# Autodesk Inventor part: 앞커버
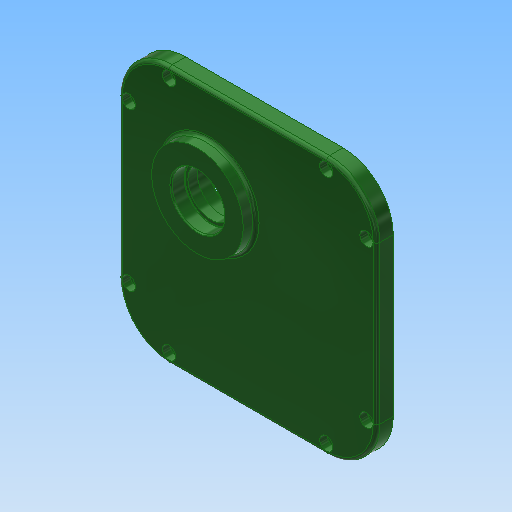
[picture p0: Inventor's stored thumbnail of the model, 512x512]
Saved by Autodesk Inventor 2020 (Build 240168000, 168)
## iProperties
Created: 2016-12
Part Number: 앞커버
Material: 알루미늄 6061
Document SubType Name: Modeling
Designer: mduedu
Density: 2.71 g/cm^3
Mass: 790.587 g
Surface Area: 580.683 cm^2
Volume: 291.729 cm^3
Appearance: 매끄러움 - 짙은 산림 녹색
Author: mduedu
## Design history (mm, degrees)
sketch "스케치1"
  geometry: L1 (-54, 50)-(-54, -44); L2 (-24, 80)-(70, 80); L3 (100, 50)-(100, -44); L4 (70, -74)-(-24, -74); A1 r 30 centre (-24, -44) between (-54, -44) and (-24, -74); A2 r 30 centre (70, 50) between (100, 50) and (70, 80); A3 r 30 centre (70, -44) between (70, -74) and (100, -44); A4 r 30 centre (-24, 50) between (-24, 80) and (-54, 50); 1 further point
  constraints: 8 end point, 8 point on circle, 8 tangent, 4 centre point, 3 equal radius, 3 perpendicular, 1 horizontal
  dimensions: "d89" = 30 radius of A2; "d90" = 100 distance from line of L3 point (0, 0); "d91" = 154 distance between parallel lines of L4 L2; "d92" = 80 distance from line of point (0, 0) L2
extrude "돌출1" new body sketch "스케치1" distance "d3" = 14; taper "d4" = 0 deg
sketch "스케치2"
  geometry: C1 r 21 at (0, 26); 1 further point
  constraints: 1 centre point, 1 vertical alignment
  dimensions: "d5" = 42 diameter of C1; "d7" = 26 distance of C1.centre point (0, 0)
extrude "돌출2" join sketch "스케치2" distance "d8" = 3; taper "d9" = 0 deg
sketch "스케치3"
  geometry: C1 r 15 at (0, -28.87); C2 r 21 at (0, 26) reference; C3 r 15 at (-54.87, 26); 1 further point
  constraints: 2 centre point, 1 horizontal alignment, 1 vertical alignment
  dimensions: "d10" = 30 diameter of C1; "d71" = 54.87 distance of C1.centre C2.centre; "d94" = 30 diameter of C3; "d95" = 54.87 distance of C2.centre C3.centre
extrude "돌출3" join sketch "스케치3" distance "d12" = 3; taper "d13" = 0 deg
sketch "스케치4"
  geometry: C1 r 21 at (0, 26) reference; C2 r 28 at (0, 26); 1 further point
  constraints: 1 centre point, 1 coincident
  dimensions: "d14" = 56 diameter of C2
extrude "돌출4" join sketch "스케치4" distance "d15" = 7; taper "d16" = -5 deg
hole "구멍1" diameter "d19" = 35; stored, may be unused: countersink angle "d23" = 90 deg, drill point angle "d25" = 0 deg; dims "d17" = 10, "d18" = 10, "d20" = 6, "d21" = 4, "d22" = 2, "d24" = 10
hole "구멍2" diameter "d28" = 22; stored, may be unused: countersink angle "d32" = 90 deg, drill point angle "d34" = 0 deg; dims "d26" = 10, "d27" = 10, "d29" = 6, "d30" = 4, "d31" = 2, "d33" = 7
hole "구멍8" diameter "d98" = 22; stored, may be unused: countersink angle "d102" = 90 deg, drill point angle "d104" = 0 deg; dims "d96" = 10, "d97" = 10, "d99" = 6, "d100" = 4, "d101" = 2, "d103" = 7
hole "구멍3" diameter "d37" = 19; stored, may be unused: countersink angle "d41" = 90 deg, drill point angle "d43" = 0 deg; dims "d38" = 6, "d39" = 4, "d40" = 2, "d42" = 3, "d127" = 10, "d128" = 10
hole "구멍9" diameter "d107" = 19; stored, may be unused: countersink angle "d111" = 90 deg, drill point angle "d113" = 0 deg; dims "d108" = 6, "d109" = 4, "d110" = 2, "d112" = 3, "d129" = 10, "d130" = 10
hole "구멍4" diameter "d46" = 32; stored, may be unused: countersink angle "d50" = 90 deg, drill point angle "d52" = 0 deg; dims "d47" = 6, "d48" = 4, "d49" = 2, "d51" = 8.3, "d121" = 10, "d122" = 10
hole "구멍5" diameter "d55" = 28; stored, may be unused: countersink angle "d59" = 90 deg, drill point angle "d61" = 0 deg; dims "d56" = 6, "d57" = 4, "d58" = 2, "d60" = 8, "d119" = 10, "d120" = 10
fillet "모깎기1" dims "d62" = 0.3
fillet "모깎기2" dims "d63" = 2
chamfer "모따기1" distance "d64" = 1; stored, may be unused: second distance "d65" = 2, angle "d66" = 45 deg
fillet "모깎기4" dims "d68" = 2
fillet "모깎기6" dims "d70" = 2
sketch "스케치5"
  geometry: L1 (70, 80)-(-24, 80) reference; L2 (100, -44)-(100, 50) reference; L3 (-24, -74)-(70, -74) reference; L4 (-54, 50)-(-54, -44) reference; L5 (-48, 50)-(-48, -44); L6 (-24, -68)-(70, -68); L7 (94, -44)-(94, 50); L8 (70, 74)-(-24, 74); A1 r 30 centre (70, 50) between (100, 50) and (70, 80) reference; A2 r 30 centre (70, -44) between (70, -74) and (100, -44) reference; A3 r 30 centre (-24, -44) between (-54, -44) and (-24, -74) reference; A4 r 30 centre (-24, 50) between (-24, 80) and (-54, 50) reference; A5 r 24 centre (-24, -44) between (-48, -44) and (-24, -68); A6 r 24 centre (70, -44) between (70, -68) and (94, -44); A7 r 24 centre (70, 50) between (94, 50) and (70, 74); A8 r 24 centre (-24, 50) between (-24, 74) and (-48, 50)
  constraints: 8 end point, 8 point on circle, 4 centre point, 7 other
  dimensions: "d93" = 6 distance between parallel lines of L5 L4
sketch "스케치7"
  geometry: L1 (70, 74)-(-24, 74) reference; L2 (94, -44)-(94, 50) reference; L3 (-24, -68)-(70, -68) reference; L4 (-48, 50)-(-48, -44) reference; A1 r 24 centre (70, 50) between (94, 50) and (70, 74) reference; A2 r 24 centre (70, -44) between (70, -68) and (94, -44) reference; A3 r 24 centre (-24, -44) between (-48, -44) and (-24, -68) reference; A4 r 24 centre (-24, 50) between (-24, 74) and (-48, 50) reference; 8 further points
  constraints: 8 coincident
hole "구멍7" sketch "스케치7" at (-48, 50), (-48, -44), (-24, -68), (70, -68), (94, -44), (94, 50), (70, 74), (-24, 74) diameter "d80" = 4.5; stored, may be unused: countersink angle "d84" = 90 deg, drill point angle "d86" = 0 deg; dims "d81" = 6, "d82" = 8, "d83" = 4.6, "d85" = 8
sketch "스케치8"
  geometry: L1 (-70, 80)-(24, 80) reference; L2 (-100, -44)-(-100, 50) reference; L3 (24, -74)-(-70, -74) reference; L4 (54, 50)-(54, -44) reference; L5 (42, -44)-(42, 50); L6 (24, 68)-(-70, 68); L7 (-88, 50)-(-88, -44); L8 (-70, -62)-(24, -62); A1 r 30 centre (-70, 50) between (-70, 80) and (-100, 50) reference; A2 r 30 centre (-70, -44) between (-100, -44) and (-70, -74) reference; A3 r 30 centre (24, 50) between (54, 50) and (24, 80) reference; A4 r 30 centre (24, -44) between (24, -74) and (54, -44) reference; A5 r 18 centre (24, 50) between (42, 50) and (24, 68); A6 r 18 centre (-70, 50) between (-70, 68) and (-88, 50); A7 r 18 centre (-70, -44) between (-88, -44) and (-70, -62); A8 r 18 centre (24, -44) between (24, -62) and (42, -44); 1 further point
  constraints: 8 end point, 8 point on circle, 4 centre point, 7 other
  dimensions: "d116" = 12 distance between parallel lines of L5 L4
extrude "돌출5" cut sketch "스케치8" distance "d117" = 4; taper "d118" = 0 deg
chamfer "모따기2" distance "d123" = 0.8; stored, may be unused: second distance "d124" = 2, angle "d125" = 30 deg
fillet "모깎기7" dims "d126" = 0.5
node "솔리드1"
